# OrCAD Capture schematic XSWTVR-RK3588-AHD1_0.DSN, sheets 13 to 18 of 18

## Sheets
13 13 Audio Codec: size Custom; note: 13 Audio Codec
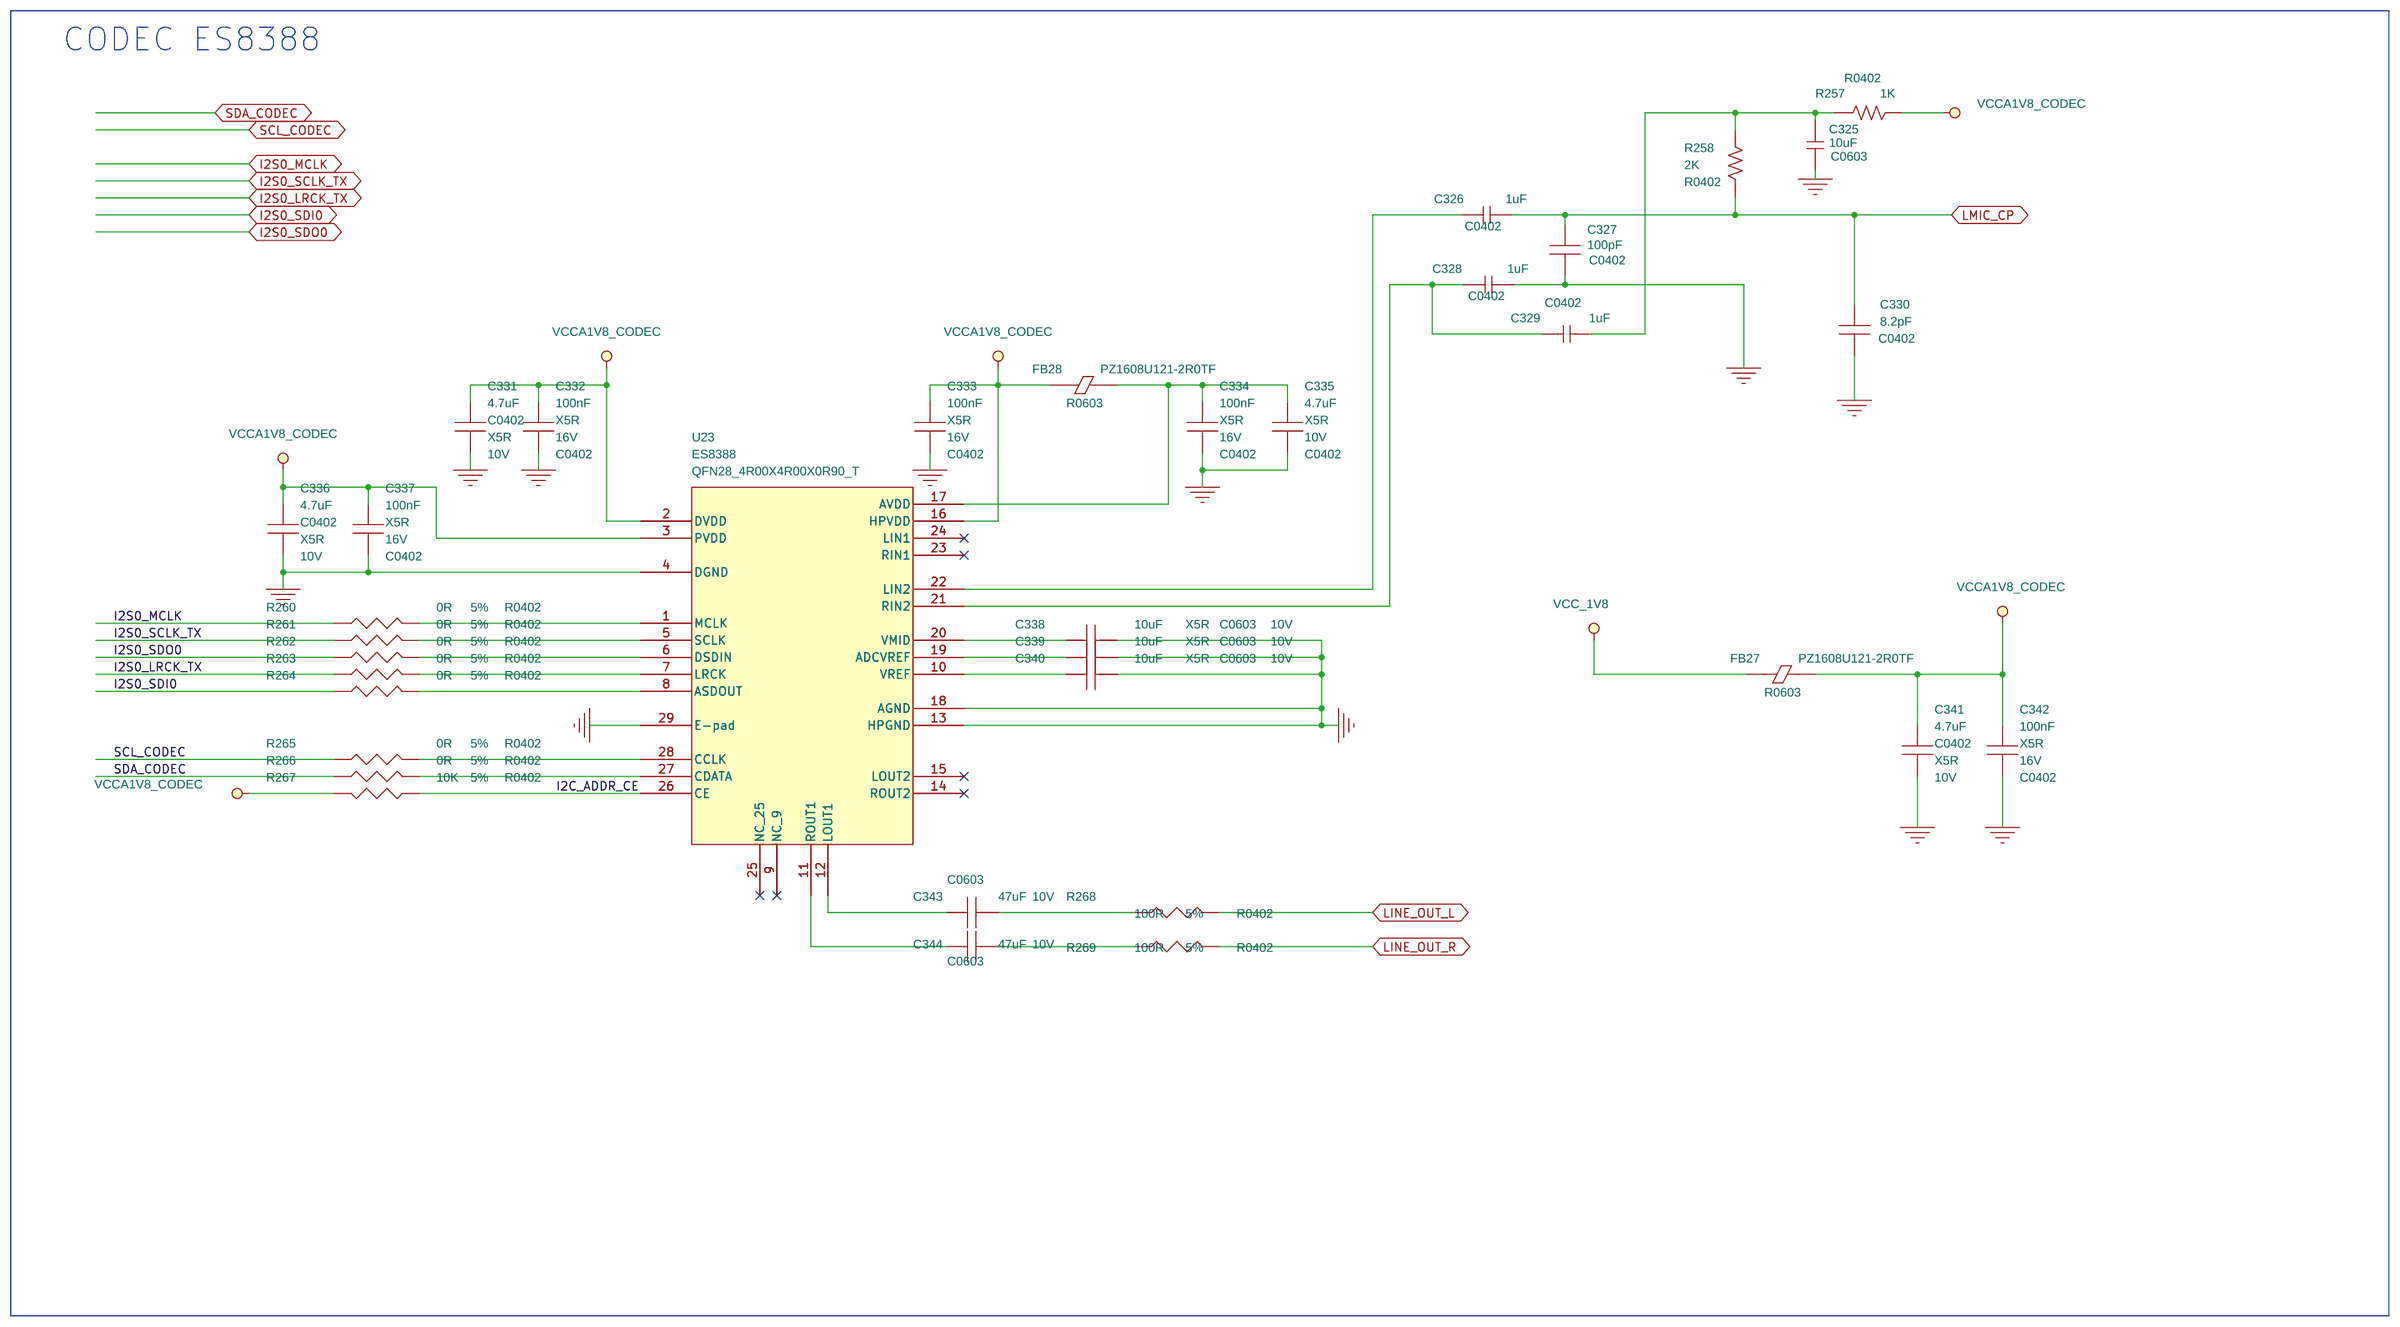
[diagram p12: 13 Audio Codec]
14 14 IO_INPUT_OUTPUT: size Custom; note: 14 IO_INPUT_OUTPUT
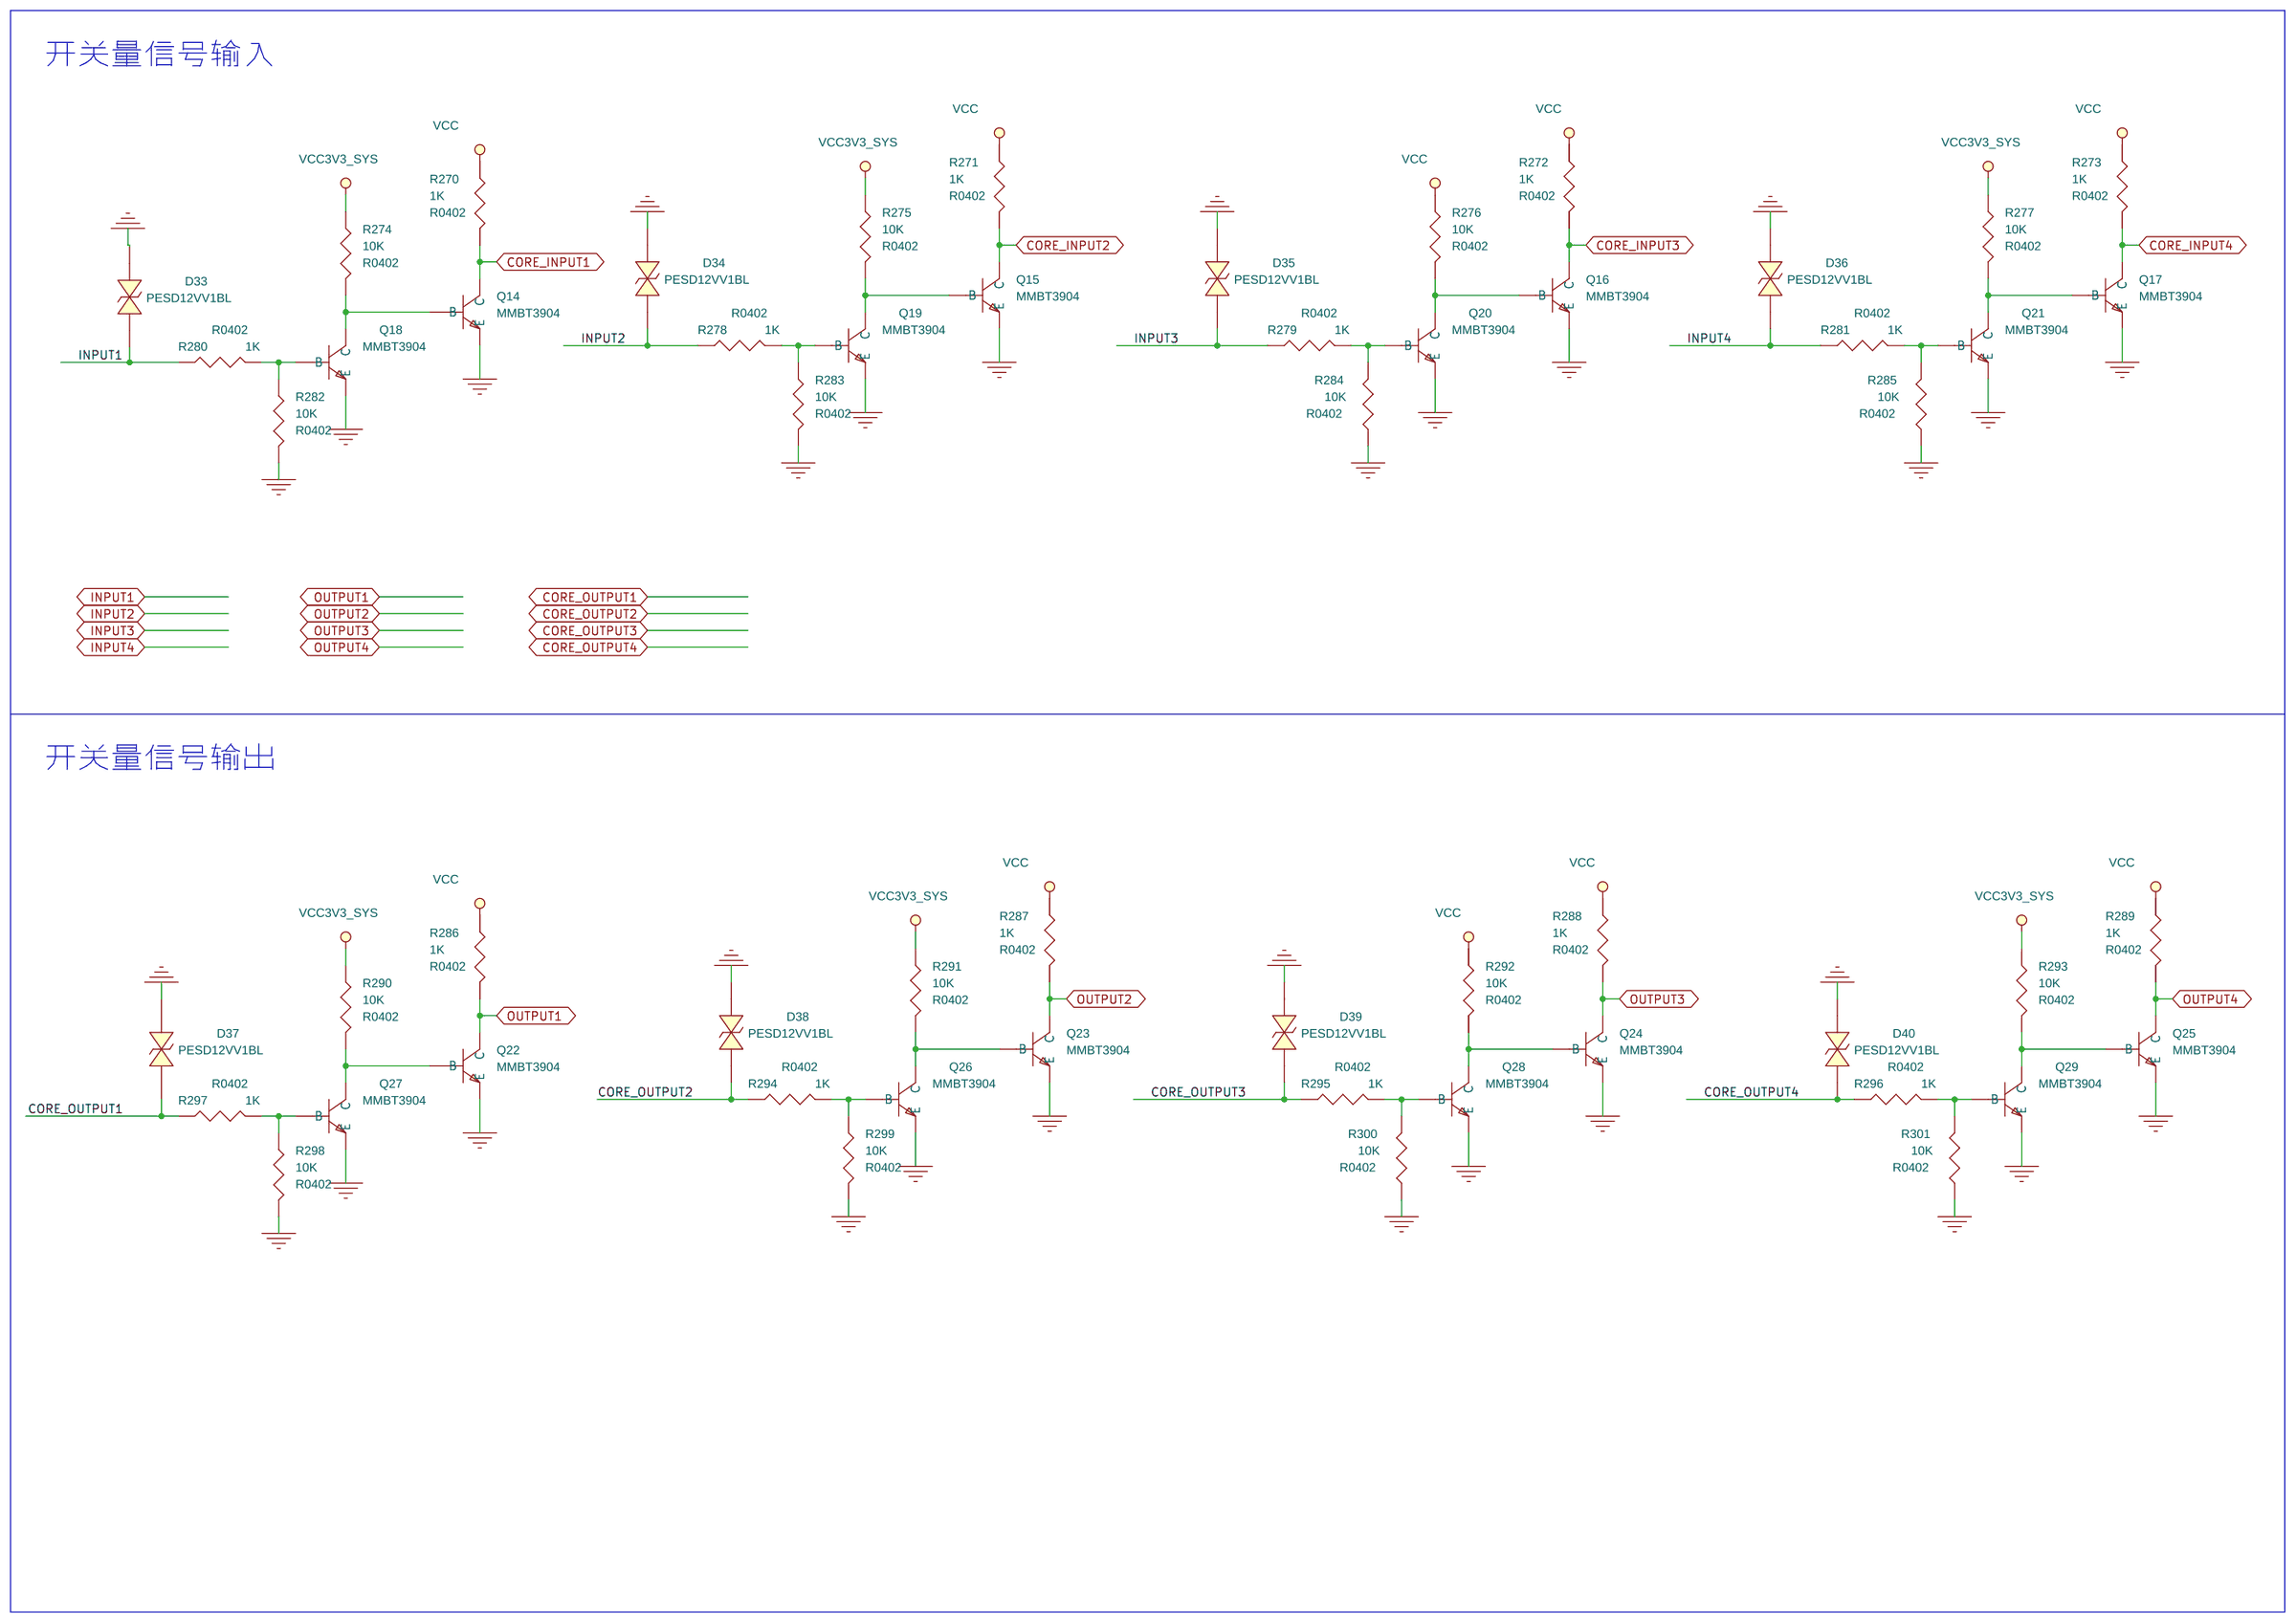
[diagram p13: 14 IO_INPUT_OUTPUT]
15 15 INTERFACE: size Custom; note: 15 INTERFACE
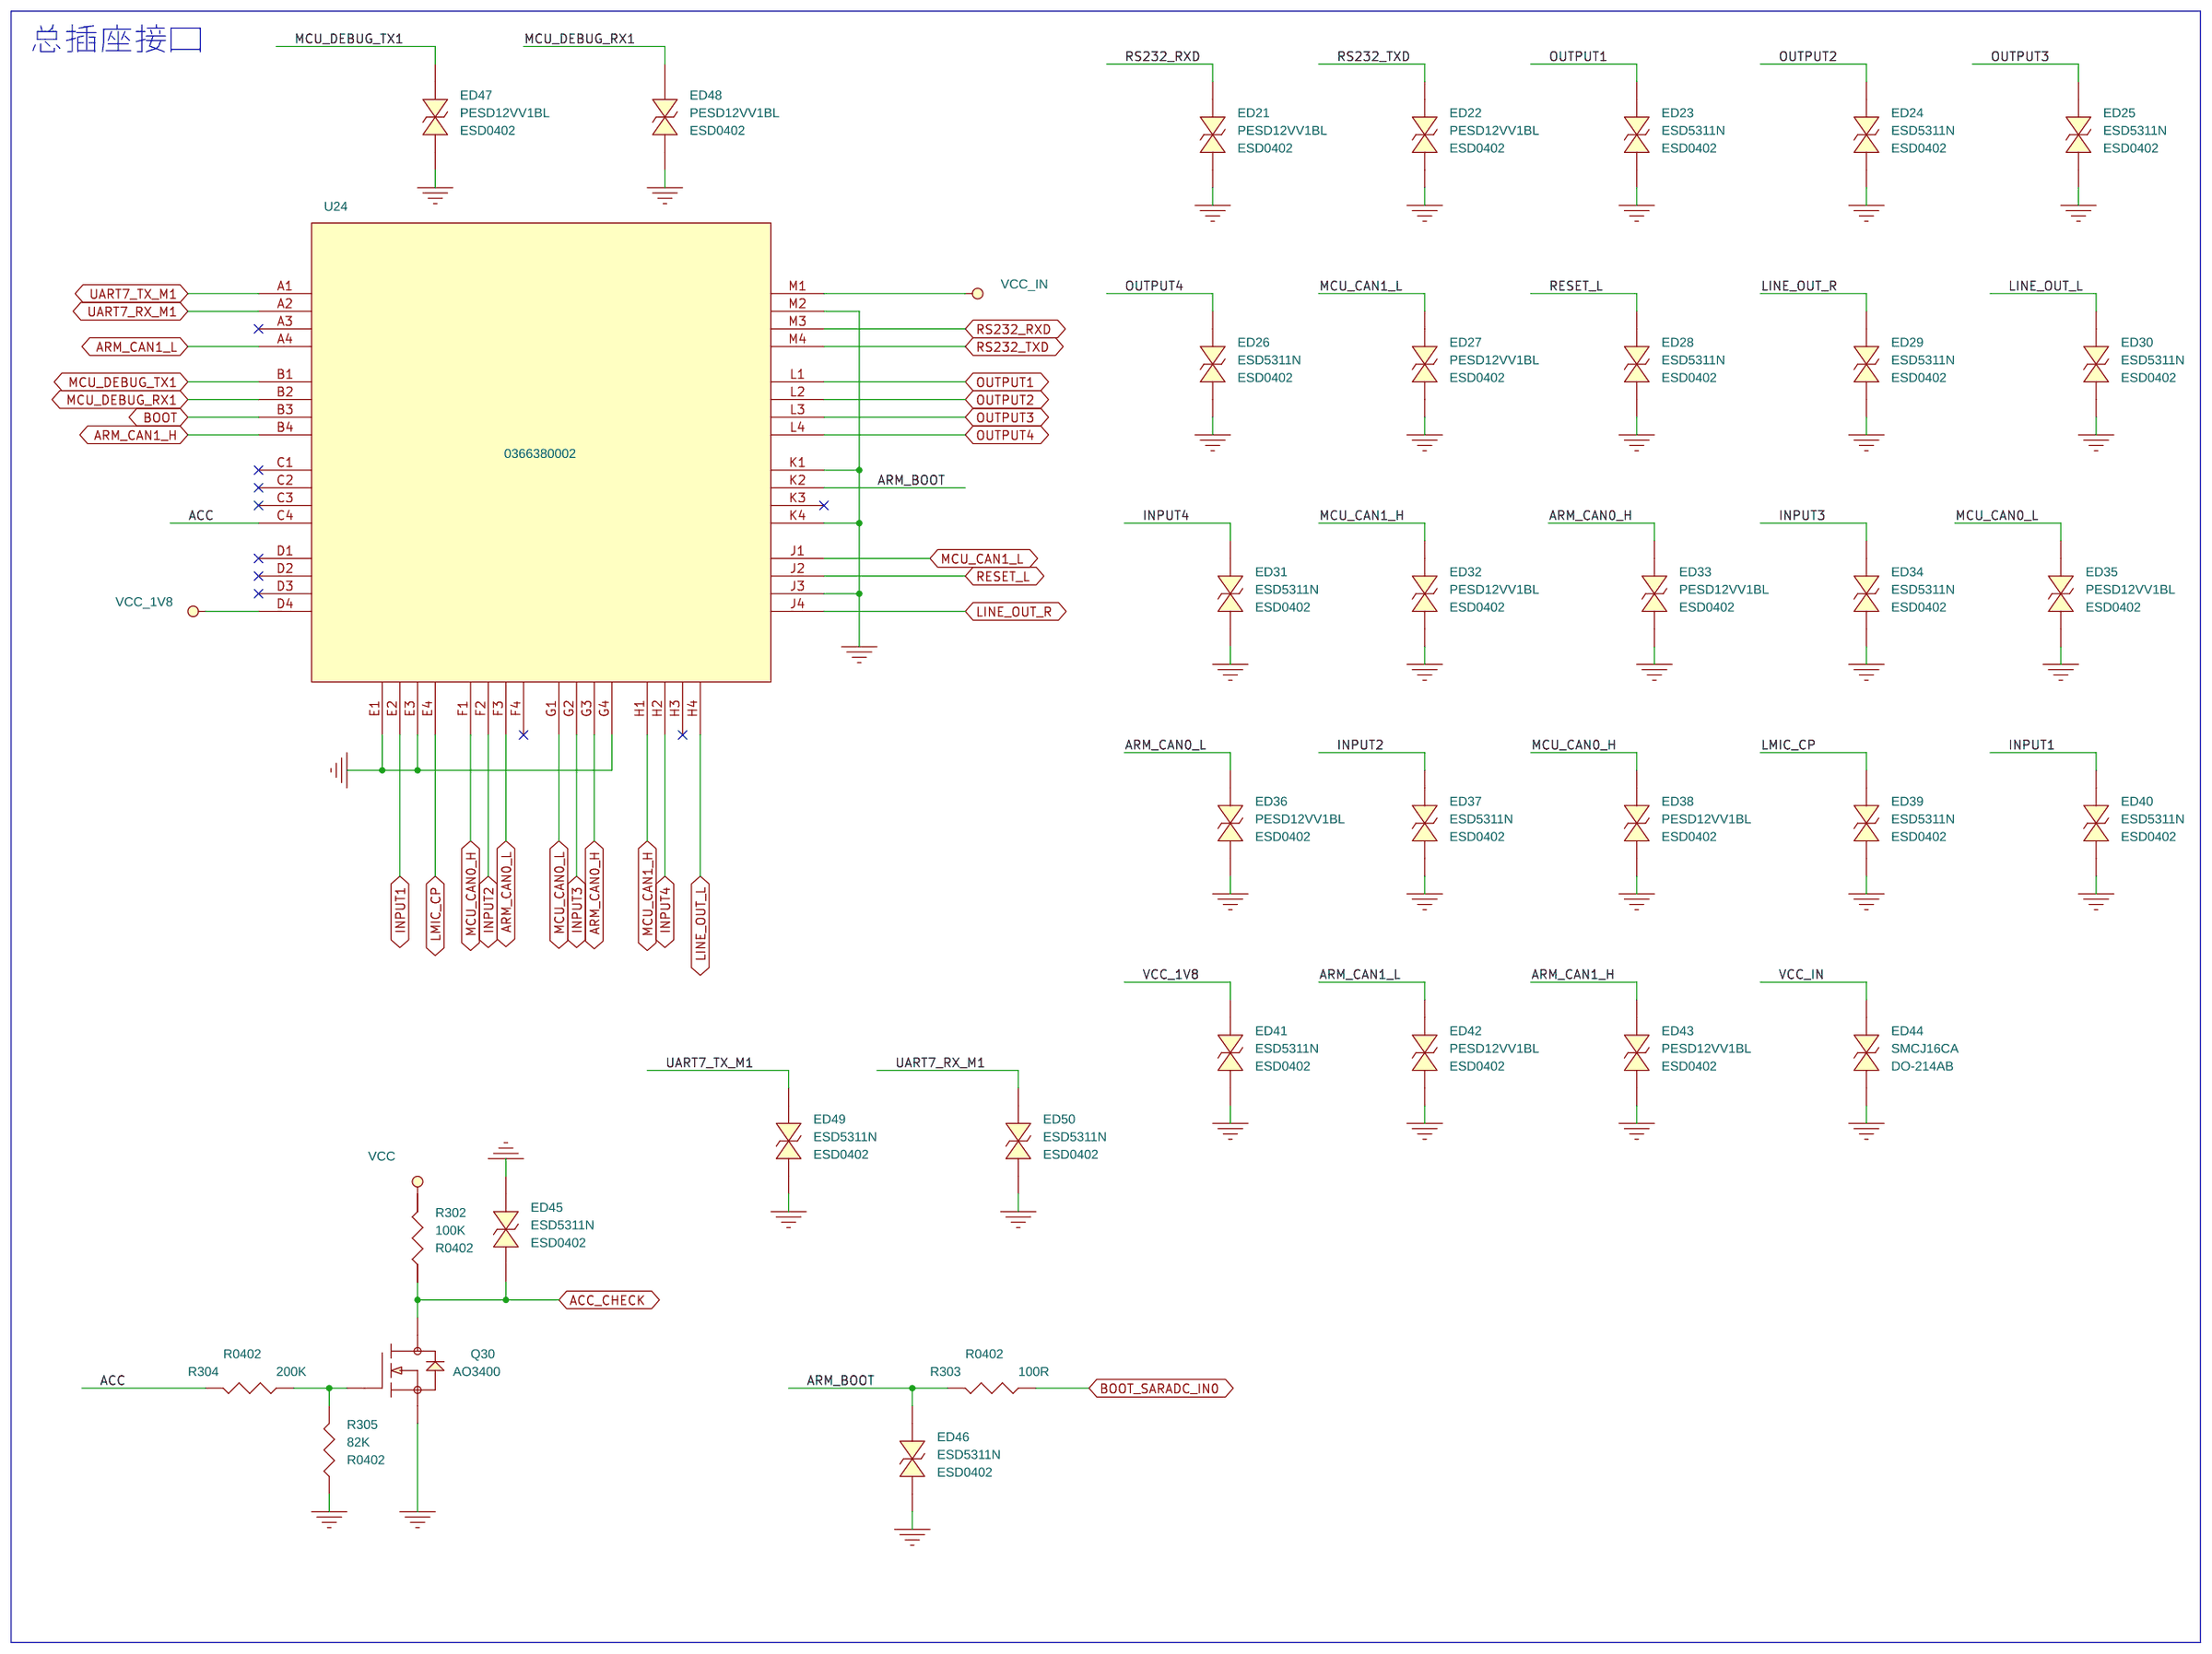
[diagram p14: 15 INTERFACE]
16 16 DEBUG&CAN: size Custom; note: 16 DEBUG&CAN
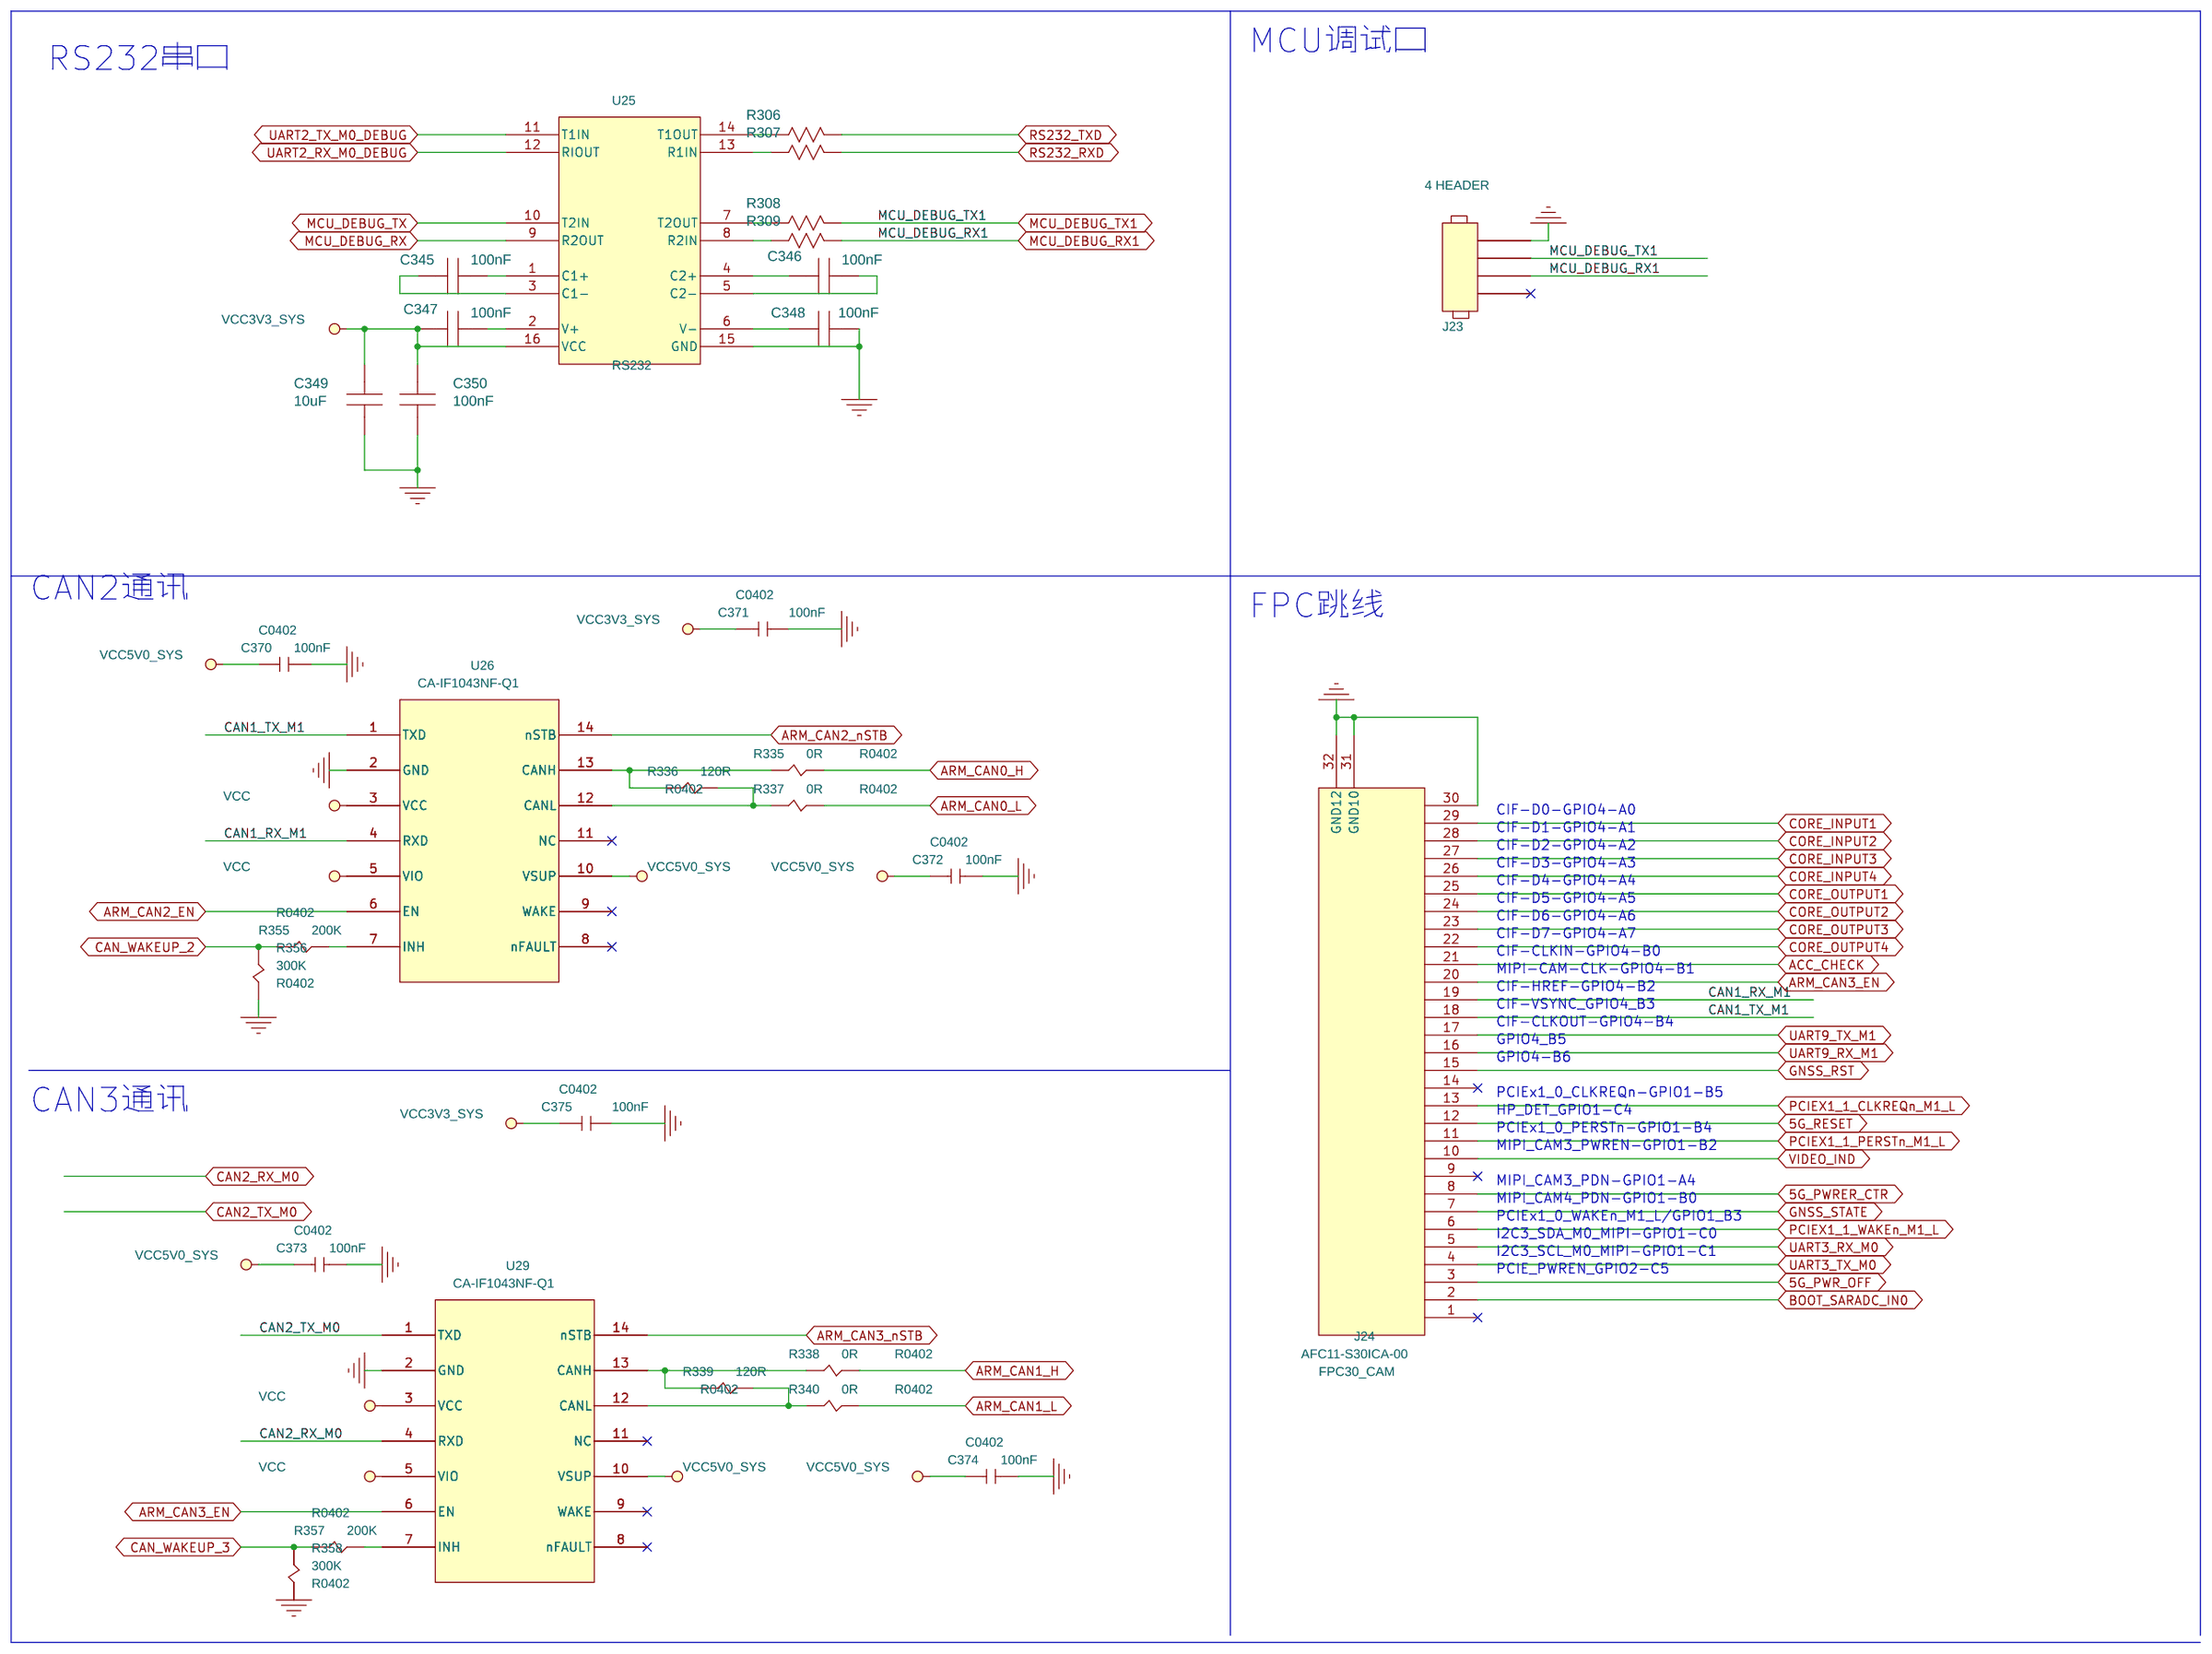
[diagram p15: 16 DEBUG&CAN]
17 17 SATA 3.0*1: size A4; rev: V1.0; note: 12.SATA *2
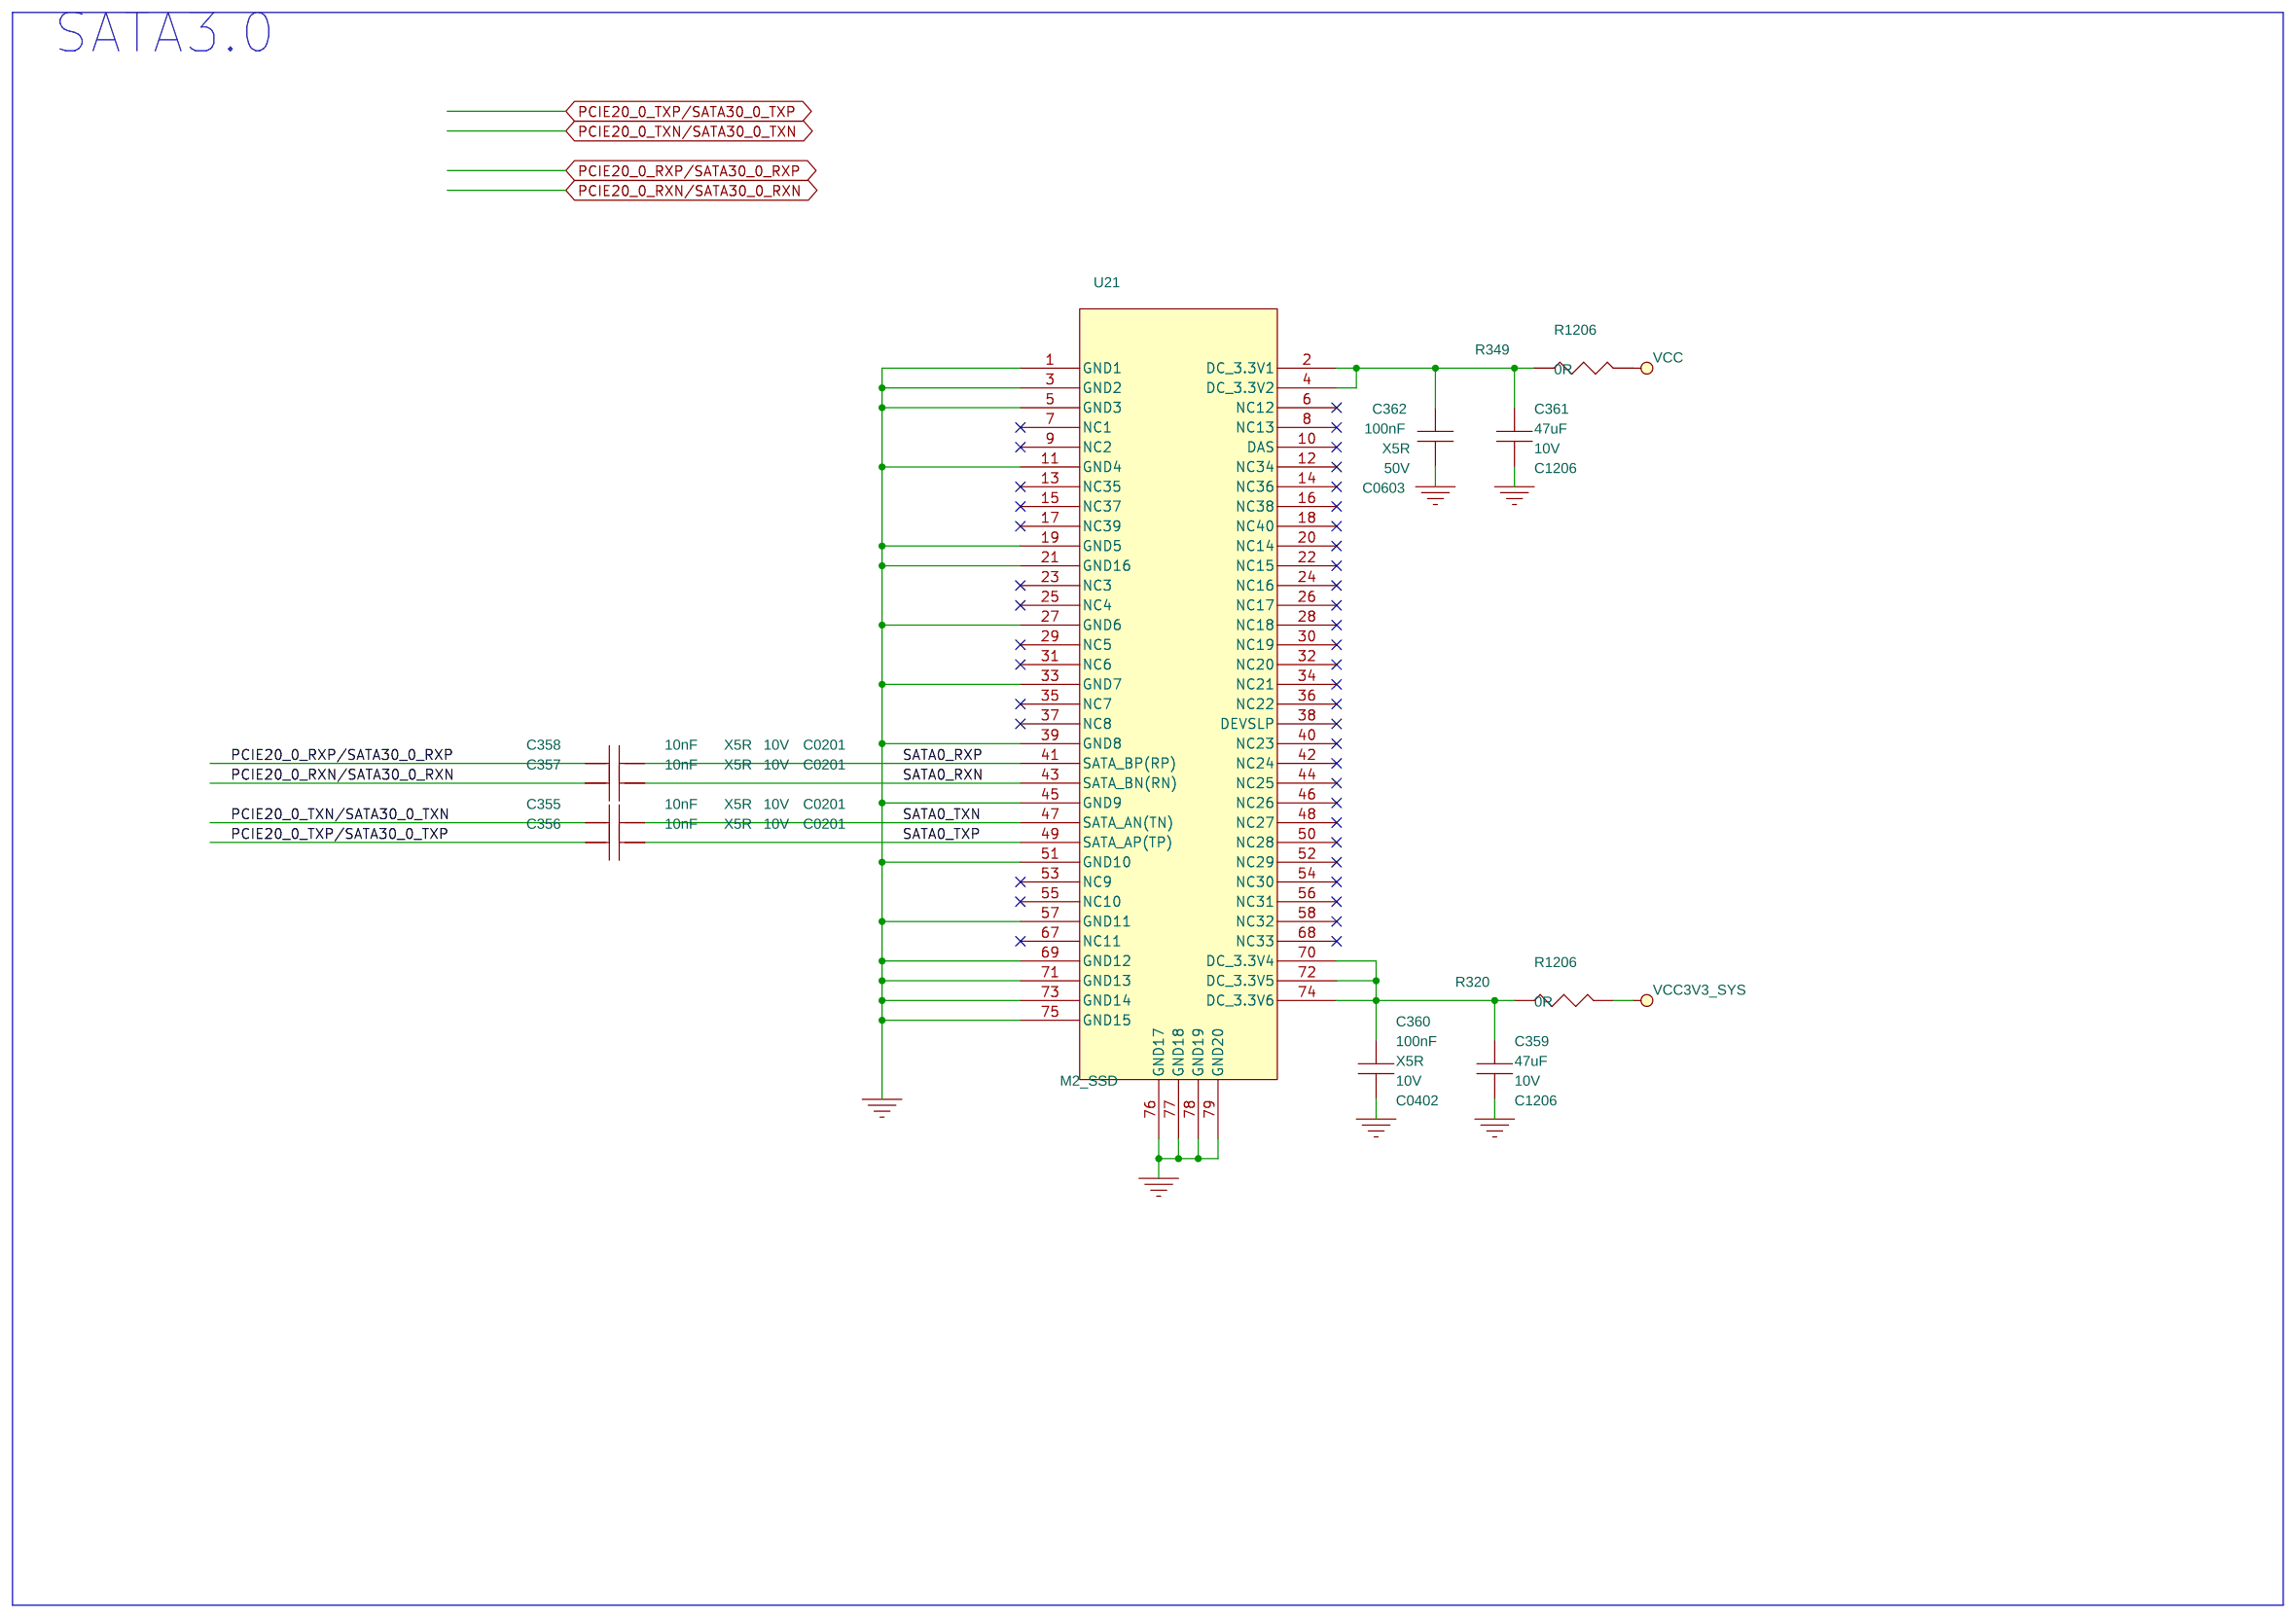
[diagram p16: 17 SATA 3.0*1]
18 18 Mark/Hole: size A4; note: 17 Mark/Hole
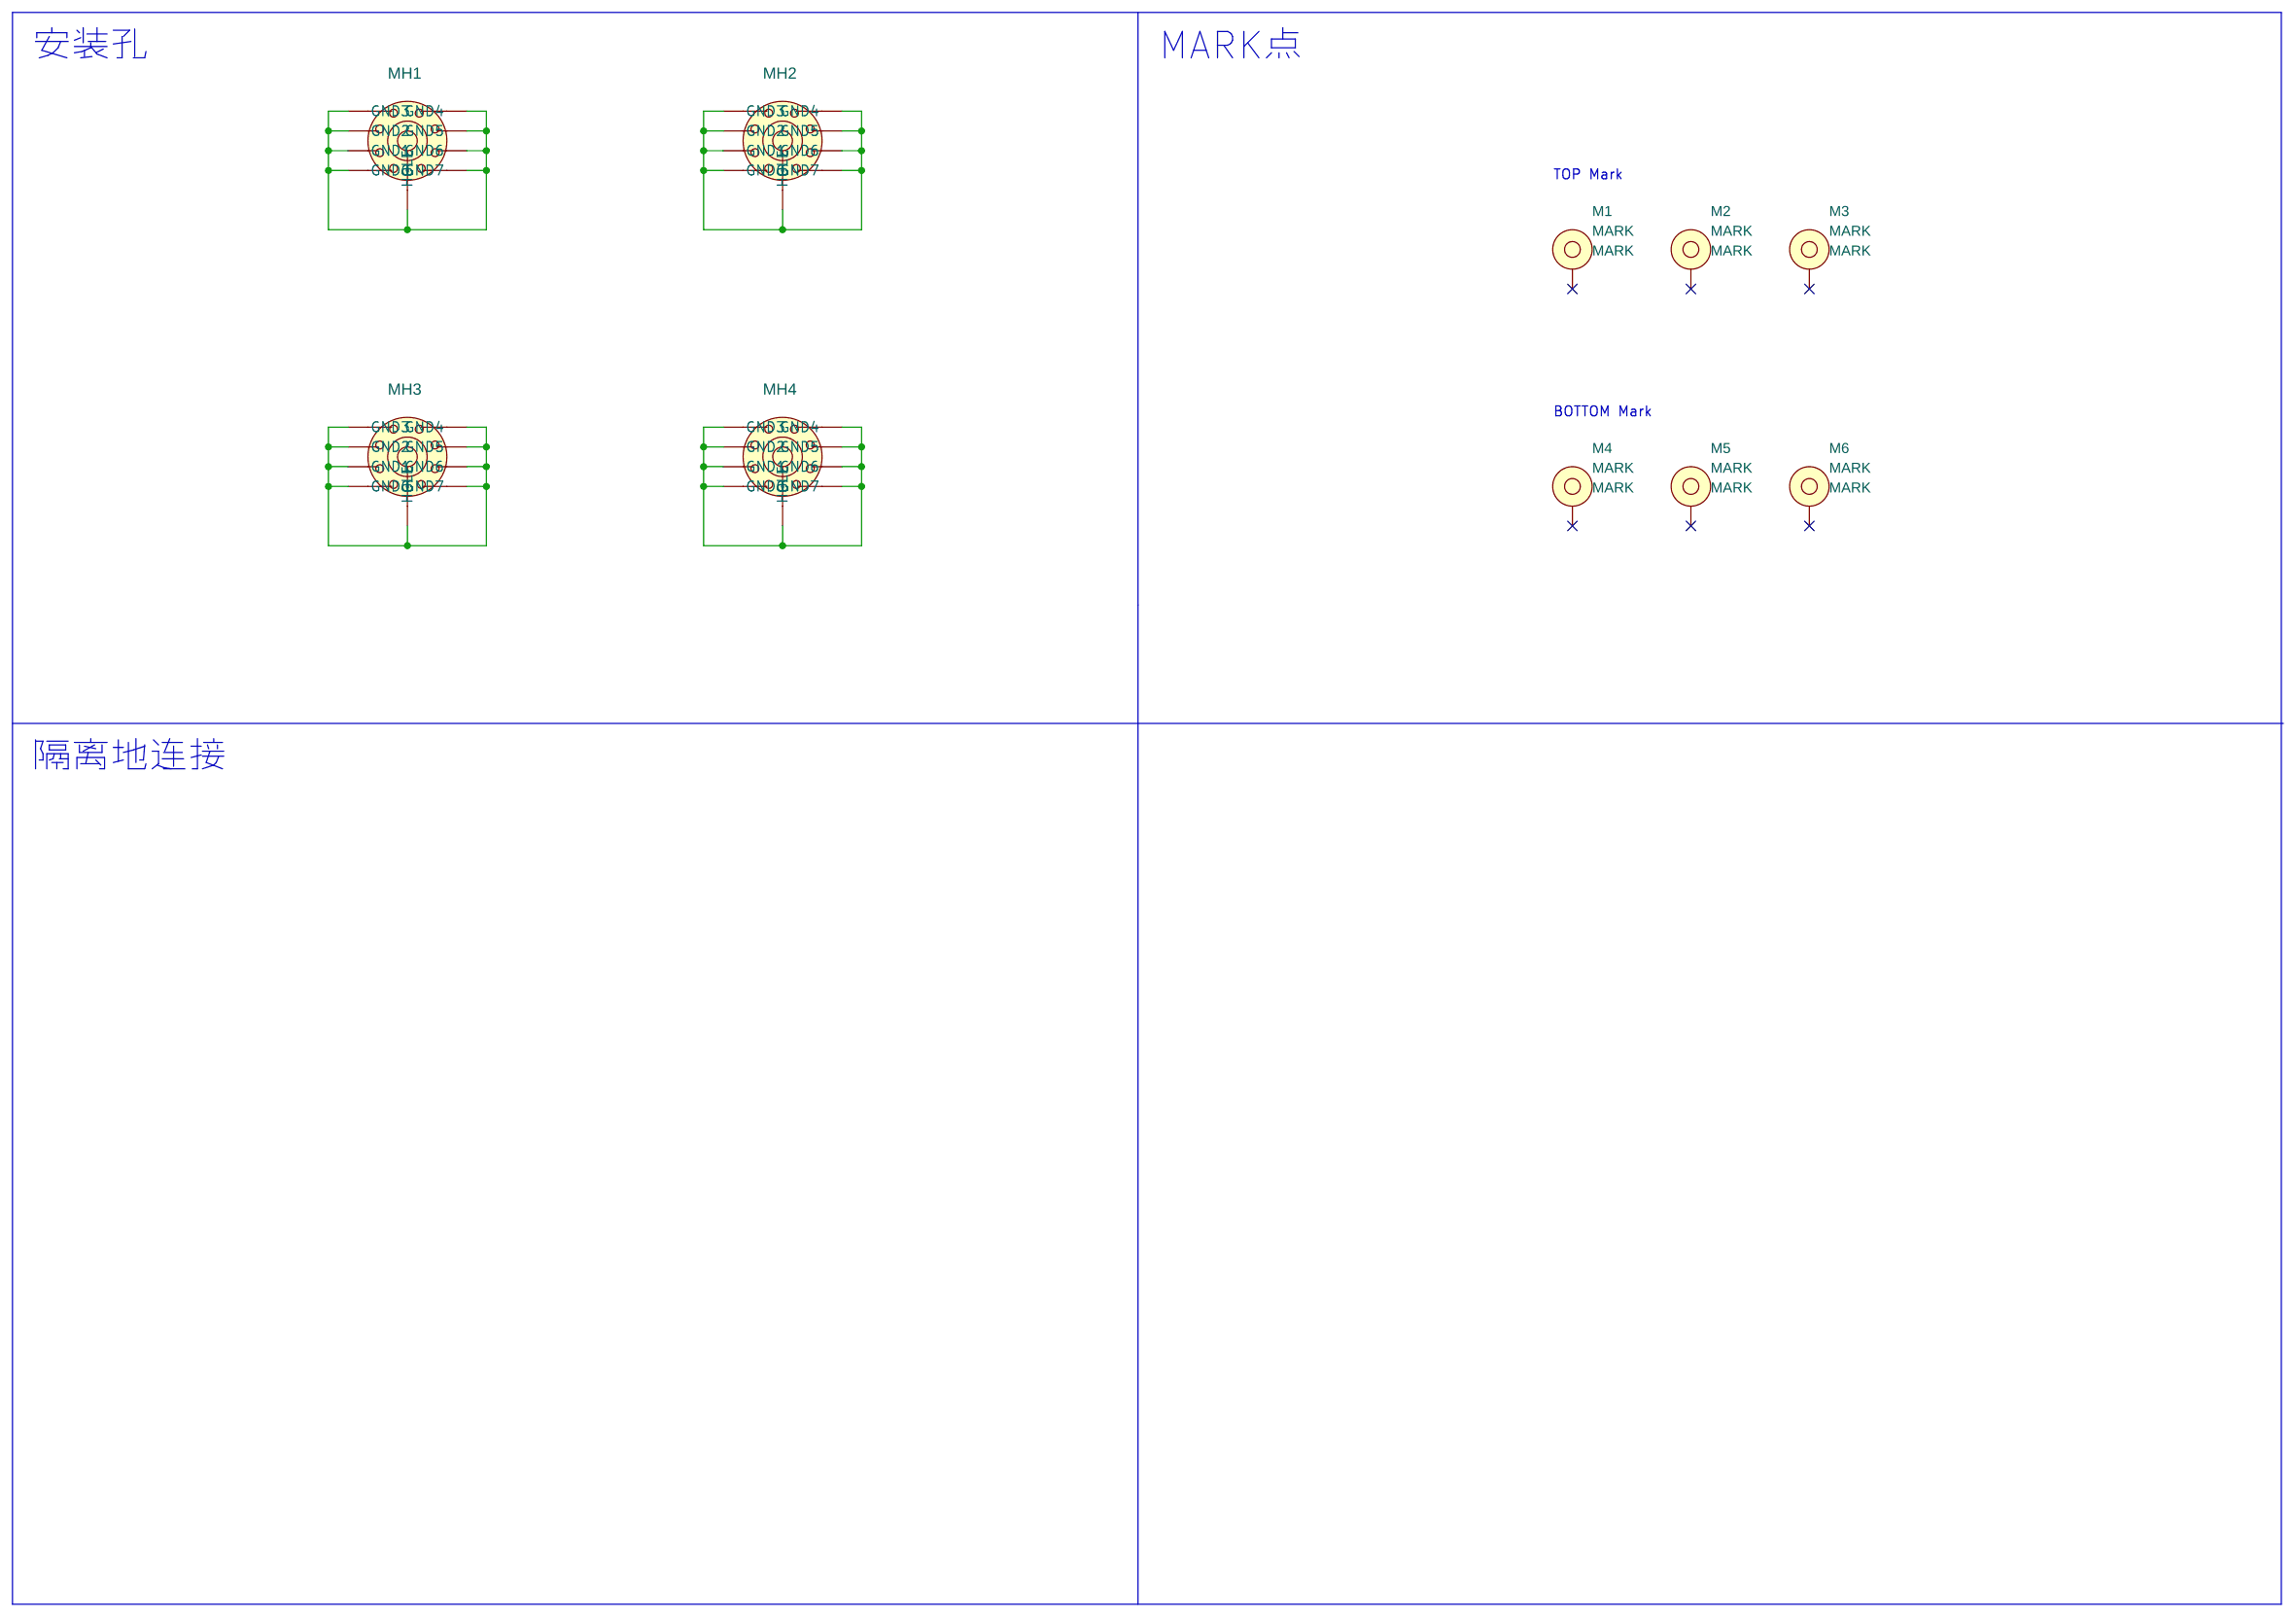
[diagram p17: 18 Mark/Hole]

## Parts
sheet 13 Audio Codec
C325  10uF  [C0603]
C326  1uF  [C0402]
C327  100pF  [C0402]
C328  1uF  [C0402]
C329  1uF  [C0402]
C330  8.2pF  [C0402]
C331  4.7uF  [C0402]
C332  100nF  [C0402]
C333  100nF  [C0402]
C334  100nF  [C0402]
C335  4.7uF  [C0402]
C336  4.7uF  [C0402]
C337  100nF  [C0402]
C338  10uF  [C0603]
C339  10uF  [C0603]
C340  10uF  [C0603]
C341  4.7uF  [C0402]
C342  100nF  [C0402]
C343  47uF  [C0603]
C344  47uF  [C0603]
FB27  PZ1608U121-2R0TF  [R0603]
FB28  PZ1608U121-2R0TF  [R0603]
R257  1K  [R0402]
R258  2K  [R0402]
R260  0R  [R0402]
R261  0R  [R0402]
R262  0R  [R0402]
R263  0R  [R0402]
R264  0R  [R0402]
R265  0R  [R0402]
R266  0R  [R0402]
R267  10K  [R0402]
R268  100R  [R0402]
R269  100R  [R0402]
U23  ES8388  [QFN28_4R00X4R00X0R90_T]
sheet 14 IO_INPUT_OUTPUT
D33  PESD12VV1BL  [esd0402]
D34  PESD12VV1BL  [esd0402]
D35  PESD12VV1BL  [esd0402]
D36  PESD12VV1BL  [esd0402]
D37  PESD12VV1BL  [esd0402]
D38  PESD12VV1BL  [esd0402]
D39  PESD12VV1BL  [esd0402]
D40  PESD12VV1BL  [esd0402]
Q14  MMBT3904  [SOT_23]
Q15  MMBT3904  [SOT_23]
Q16  MMBT3904  [SOT_23]
Q17  MMBT3904  [SOT_23]
Q18  MMBT3904  [SOT_23]
Q19  MMBT3904  [SOT_23]
Q20  MMBT3904  [SOT_23]
Q21  MMBT3904  [SOT_23]
Q22  MMBT3904  [SOT_23]
Q23  MMBT3904  [SOT_23]
Q24  MMBT3904  [SOT_23]
Q25  MMBT3904  [SOT_23]
Q26  MMBT3904  [SOT_23]
Q27  MMBT3904  [SOT_23]
Q28  MMBT3904  [SOT_23]
Q29  MMBT3904  [SOT_23]
R270  1K  [R0402]
R271  1K  [R0402]
R272  1K  [R0402]
R273  1K  [R0402]
R274  10K  [R0402]
R275  10K  [R0402]
R276  10K  [R0402]
R277  10K  [R0402]
R278  1K  [R0402]
R279  1K  [R0402]
R280  1K  [R0402]
R281  1K  [R0402]
R282  10K  [R0402]
R283  10K  [R0402]
R284  10K  [R0402]
R285  10K  [R0402]
R286  1K  [R0402]
R287  1K  [R0402]
R288  1K  [R0402]
R289  1K  [R0402]
R290  10K  [R0402]
R291  10K  [R0402]
R292  10K  [R0402]
R293  10K  [R0402]
R294  1K  [R0402]
R295  1K  [R0402]
R296  1K  [R0402]
R297  1K  [R0402]
R298  10K  [R0402]
R299  10K  [R0402]
R300  10K  [R0402]
R301  10K  [R0402]
sheet 15 INTERFACE
ED21  PESD12VV1BL  [ESD0402]
ED22  PESD12VV1BL  [ESD0402]
ED23  ESD5311N  [ESD0402]
ED24  ESD5311N  [ESD0402]
ED25  ESD5311N  [ESD0402]
ED26  ESD5311N  [ESD0402]
ED27  PESD12VV1BL  [ESD0402]
ED28  ESD5311N  [ESD0402]
ED29  ESD5311N  [ESD0402]
ED30  ESD5311N  [ESD0402]
ED31  ESD5311N  [ESD0402]
ED32  PESD12VV1BL  [ESD0402]
ED33  PESD12VV1BL  [ESD0402]
ED34  ESD5311N  [ESD0402]
ED35  PESD12VV1BL  [ESD0402]
ED36  PESD12VV1BL  [ESD0402]
ED37  ESD5311N  [ESD0402]
ED38  PESD12VV1BL  [ESD0402]
ED39  ESD5311N  [ESD0402]
ED40  ESD5311N  [ESD0402]
ED41  ESD5311N  [ESD0402]
ED42  PESD12VV1BL  [ESD0402]
ED43  PESD12VV1BL  [ESD0402]
ED44  SMCJ16CA  [DO-214AB]
ED45  ESD5311N  [ESD0402]
ED46  ESD5311N  [ESD0402]
ED47  PESD12VV1BL  [ESD0402]
ED48  PESD12VV1BL  [ESD0402]
ED49  ESD5311N  [ESD0402]
ED50  ESD5311N  [ESD0402]
Q30  AO3400  [SOT_23]
R302  100K  [R0402]
R303  100R  [R0402]
R304  200K  [R0402]
R305  82K  [R0402]
U24  0366380002  [SOCKET_PLUG_0366380002]
sheet 16 DEBUG&CAN
C345  100nF  [C0402]
C346  100nF  [C0402]
C347  100nF  [C0402]
C348  100nF  [C0402]
C349  10uF  [C0603]
C350  100nF  [C0402]
C370  100nF  [C0402]
C371  100nF  [C0402]
C372  100nF  [C0402]
C373  100nF  [C0402]
C374  100nF  [C0402]
C375  100nF  [C0402]
J23  4 HEADER  [SOCKET_4P_2P54]
J24  AFC11-S30ICA-00  [FPC30_CAM]
R306  100R  [R0402]
R307  100R  [R0402]
R308  100R  [R0402]
R309  100R  [R0402]
R335  0R  [R0402]
R336  120R  [R0402]
R337  0R  [R0402]
R338  0R  [R0402]
R339  120R  [R0402]
R340  0R  [R0402]
R355  200K  [R0402]
R356  300K  [R0402]
R357  200K  [R0402]
R358  300K  [R0402]
U25  RS232  [IC_SSOP_16]
U26  CA-IF1043NF-Q1  [IC_SOIC_14]
U29  CA-IF1043NF-Q1  [IC_SOIC_14]
sheet 17 SATA 3.0*1
C355  10nF  [C0201]
C356  10nF  [C0201]
C357  10nF  [C0201]
C358  10nF  [C0201]
C359  47uF  [C1206]
C360  100nF  [C0402]
C361  47uF  [C1206]
C362  100nF  [C0603]
R320  0R  [R1206]
R349  0R  [R1206]
U21  M2_SSD  [M2_SSD_2240_2280]
sheet 18 Mark/Hole
M1  MARK  [MARK]
M2  MARK  [MARK]
M3  MARK  [MARK]
M4  MARK  [MARK]
M5  MARK  [MARK]
M6  MARK  [MARK]
MH1  HOLE-8STARS  [hole_3_5mm]
MH2  HOLE-8STARS  [hole_3_5mm]
MH3  HOLE-8STARS  [hole_3_5mm]
MH4  HOLE-8STARS  [hole_3_5mm]

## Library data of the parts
C325 C326 C328 C329 = C_0: REUSE_ANNOTATE: TRUE
C327 C330 = CAP_v2: Capacitor-100nF,+/-10%,X5R,25V-0402; Part Number: 02.0038.00; Part Type: 0402表贴普通电容; REUSE_ANNOTATE: TRUE; 供应商: 国巨 / Murata; 规格型号1: CC0402KRX5R8BB104 / GRM155R71E104KE14D; 联系人: 谢苏云; 手机: 15900554174; 邮箱: susan.xie@murata.com
C331 C335 C336 C341 = CAP_NP: cap,4.70uF,+/-10%,10V,X5R,C0402; Created by: JJJ; Dielectric: X5R; Manufacturer: TDK; Manufacturer PN: C1005X5R1A475K050BC; Priority: A; RK PN: C1005X5R1A475K050BC; Tolerance: 10%; Voltage: 10V
C332-C334 C337 C342 = CAP_NP: cap,100.00nF,+/-10%,16V,X5R,C0402; Created by: JJJ; Dielectric: X5R; Manufacturer: TDK; Manufacturer PN: C1005X5R1C104K050BA; Priority: A; RK PN: C1005X5R1C104K050BA; Tolerance: 10%; Voltage: 16V
C338-C340 = CAP_NP: cap,10.00uF,+/-10%,10V,X5R,C0603; Created by: JJJ; Dielectric: X5R; Manufacturer: TDK; Manufacturer PN: C1608X5R1A106K080AC; Priority: A; RK PN: C1608X5R1A106K080AC; Tolerance: 10%; Voltage: 10V
C343 C344 C359 C361 = CAP_NP_0: cap,10.00uF,+/-10%,25V,X5R,C1206; C_Voltage: 6.3V; Created by: JJJ; Dielectric: X5R; Manufacturer: TDK; Manufacturer PN: C3216X5R1E106K085AC; Priority: A; RK PN: C3216X5R1E106K085AC; Tolerance: 10%; Voltage: 10V
FB27 FB28 = FB: Part Type: R0402
R257 R258 = R: REUSE_ANNOTATE: TRUE
R260-R266 = RESISTOR: 通用厚膜电阻,0R,+/-5%,R0402,1/16W.; Created by: YTL; Manufacturer: YAGEO; Manufacturer PN: RC0402JR-070RL; Part Type: 通用厚膜电阻; Priority: A; RK PN: RC0402JR-070RL; Tolerance: 5%; Wattage: 1/16W
R267 = RESISTOR: 通用厚膜电阻,10K,+/-5%,R0402,1/16W.; Created by: YTL; Manufacturer: YAGEO; Manufacturer PN: RC0402JR-0710KL; Part Type: 通用厚膜电阻; Priority: A; RK PN: RC0402JR-0710KL; Tolerance: 5%; Wattage: 1/16W
R268 R269 = RESISTOR: 通用厚膜电阻,1K1,+/-5%,R0402,1/16W.; Created by: YTL; Manufacturer: YAGEO; Manufacturer PN: RC0402JR-071K1L; Part Type: 通用厚膜电阻; Priority: A; RK PN: RC0402JR-071K1L; Tolerance: 5%; Wattage: 1/16W
U23 = Amplifier_ES8388: ES8388 is a high performance, low power and low cost audio CODEC. It consists of 2-ch ADC, 2-ch DAC, microphone amplifier, headphone amplifier, digital sound effects, and analog mixing and gain functions.; Created by: JJJ; Manufacturer: Everest（顺芯）; Part Type: Amplifier; Priority: A
D33-D40 = DIODE_DIAC
Q14-Q29 = NPN_3
R270-R273 R278-R281 R286-R289 R294-R297 R302-R305 = R_0
R274-R277 R282-R285 R290-R293 R298-R301 = RESISTOR_0: 通用厚膜电阻,232K,+/-1%,R0402,1/16W.; Created by: YTL; Manufacturer: YAGEO; Manufacturer PN: RC0402FR-07232KL; Part Type: 通用厚膜电阻; Priority: A; RK PN: RC0402FR-07232KL; Tolerance: 5%; Wattage: 1/16W
ED21 ED22 ED27 ED32 ED33 ED35 ED36 ED38 ED42-ED44 ED47 ED48 = DIODE_BI_DIR_TRIG: 1-Line, Bi-directional, Transient Voltage Suppressors.0.25pF.; Created by: JJJ; Manufacturer: WillSemi(韦尔半导体); Manufacturer PN: ESD5311N; Part Type: ESD_TVS; Priority: A; RK PN: ESD5311N
ED23-ED26 ED28-ED31 ED34 ED37 ED39-ED41 ED45 ED46 ED49 ED50 = DIODE_BI_DIR_TRIG: 1-Line, Bi-directional, Transient Voltage Suppressors.0.25pF.; Created by: JJJ; Manufacturer: WillSemi(韦尔半导体); Part Type: ESD_TVS; Priority: A
Q30 = 2N6660
U24 = 0366380002
C345-C348 C350 = C_2: %182%%238%%182%%168%%185%%164%%215%%247%%181%%231%%209%%185%(V): 10; %195%%232%%202%%246%: SMD陶瓷电容-10V-1000NF-+/-10%-X5R-0402-BT,TS16949; %208%%161%%192%%224%%195%%251%%179%%198%: SMD陶瓷电容; CODE: 8070612; COMPONENT_HIGH_MAX: 0.55MM; DEVICE: CV05X5R105K10AH; PKG_TYPE: SC0402; SIGNAL_MODEL: DEFAULT_CAPACITOR_1e+06pF_1_2
C349 = C: %182%%238%%182%%168%%185%%164%%215%%247%%181%%231%%209%%185%(V): 25; %195%%232%%202%%246%: SMD陶瓷电容-25V-10000NF-+/-20%-X5R-0805; %208%%161%%192%%224%%195%%251%%179%%198%: SMD陶瓷电容; CODE: 8071629; COMPONENT_HIGH_MAX: 1.45MM; PKG_TYPE: SC0805; SIGNAL_MODEL: DEFAULT_CAPACITOR_1e+07pF_1_2
C370-C375 = CAP_NP_1: price: 0.0125
J23 = 4_HEADER
J24 = LD089WU1_0
R306-R309 = R_v2: %195%%232%%202%%246%: 片式厚膜电阻器-0.0625W-10000ohm-+/-5%-0402-BT; %208%%161%%192%%224%%195%%251%%179%%198%: 片式厚膜电阻器; CODE: 7090815; COMPONENT_HIGH_MAX: 0.4mm; PKG_TYPE: SR0402
R335-R340 R355-R358 = SR_1: price: 0.000688
U25 = RS232_0
U26 U29 = CA-IF1043NF-Q1
C355-C358 = CAP_NP: cap,10.00nF,+/-10%,10V,X5R,C0201; Created by: JJJ; Dielectric: X5R; Manufacturer: TDK; Manufacturer PN: C0603X5R1A103K030BA; Priority: A; RK PN: C0603X5R1A103K030BA; Tolerance: 10%; Voltage: 10V
C360 = CAP_NP: cap,100.00nF,+/-10%,10V,X5R,C0402; C_Voltage: 6.3V; Created by: JJJ; Dielectric: X5R; Manufacturer: TDK; Manufacturer PN: C1005X5R1A104K050BA; Number: 37; Priority: A; RK PN: C1005X5R1A104K050BA; Tolerance: 10%; Voltage: 10V
C362 = CAP_NP: cap,100.00nF,+/-10%,50V,X5R,C0603; Created by: JJJ; Dielectric: X5R; Manufacturer: TDK; Manufacturer PN: C1608X5R1H104K080AA; Priority: A; RK PN: C1608X5R1H104K080AA; Tolerance: 10%; Voltage: 50V
R320 R349 = RESISTOR: 通用厚膜电阻,0R,+/-5%,R1206,1/4W.; Created by: YTL; Manufacturer: YAGEO; Manufacturer PN: RC1206JR-070RL; Part Type: 通用厚膜电阻; Priority: A; RK PN: RC1206JR-070RL; Tolerance: 5%; Wattage: 1/4W
U21 = M2-SSD_1
M1-M6 = MARK: MARK Symble; Created by: JJJ; Priority: A; RK PN: MARK01
MH1-MH4 = HOLE-8STARS_1: %195%%232%%202%%246%: M3螺钉(推荐使用)，对应138MIL星月孔，适用于过波峰焊设计。; PKG_TYPE: HOLE160-8STAR

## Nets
DGND: C325.2 C327.2 C328.1 C330.2 C331.2 C332.2 C333.2 C334.2 C335.2 C336.2 C337.2 C338.2 C339.2 C340.2 C341.2 C342.2 C348.2(B) C349.2(B) C350.1(A) C359.2 C360.2 C361.2 C362.2 C370.2 C371.1 C372.2 C373.2 C374.2 C375.1 D33.2 D34.2 D35.2 D36.2 D37.2 D38.2 D39.2 D40.2 ED21.2 ED22.2 ED23.2 ED24.2 ED25.2 ED26.2 ED27.2 ED28.2 ED29.2 ED30.2 ED31.2 ED32.2 ED33.2 ED34.2 ED35.2 ED36.2 ED37.2 ED38.2 ED39.2 ED40.2 ED41.2 ED42.2 ED43.2 ED44.2 ED45.1 ED46.2 ED47.2 ED48.2 ED49.2 ED50.2 J23.4 J24.30 J24.31(GND10) J24.32(GND12) Q14.2(E) Q15.2(E) Q16.2(E) Q17.2(E) Q18.2(E) Q19.2(E) Q20.2(E) Q21.2(E) Q22.2(E) Q23.2(E) Q24.2(E) Q25.2(E) Q26.2(E) Q27.2(E) Q28.2(E) Q29.2(E) Q30.2(S) R282.2 R283.2 R284.2 R285.2 R298.2 R299.2 R300.2 R301.2 R305.1 R356.1 R358.1 U21.1(GND1) U21.3(GND2) U21.5(GND3) U21.11(GND4) U21.19(GND5) U21.21(GND16) U21.27(GND6) U21.33(GND7) U21.39(GND8) U21.45(GND9) U21.51(GND10) U21.57(GND11) U21.69(GND12) U21.71(GND13) U21.73(GND14) U21.75(GND15) U21.76(GND17) U21.77(GND18) U21.78(GND19) U21.79(GND20) U23.4(DGND) U23.13(HPGND) U23.18(AGND) U23.29(E-pad) U24.E1 U24.E3 U24.G4 U24.J3 U24.K1 U24.K4 U24.M2 U25.15(GND) U26.2(GND) U29.2(GND) ; also on sheet 1 2 3 4 5 6 7 8 9 10 11 12
VCC3V3_SYS: C347.1(A) C349.1(A) C350.2(B) C371.2 C375.2 R270.2 R271.2 R272.2 R273.2 R274.1 R275.1 R276.1 R277.1 R286.2 R287.2 R288.2 R289.2 R290.1 R291.1 R292.1 R293.1 R302.2 R320.2 R349.2 U25.16(VCC) U26.5(VIO) U29.5(VIO) ; also on sheet 1 3 4 5 6 7 8 9 10 11 12
VCC5V0_SYS: C370.1 C372.1 C373.1 C374.1 U26.3(VCC) U26.10(VSUP) U29.3(VCC) U29.10(VSUP) ; also on sheet 1 3 4 8
VCC_1V8: ED41.1 FB27.1 U24.D4 ; also on sheet 3 4 8 9 10
VCC_IN: ED44.1 U24.M1 ; also on sheet 3
VCCA1V8_CODEC: C331.1 C332.1 C333.1 C336.1 C337.1 C341.1 C342.1 FB27.2 FB28.1 R257.2 R267.2 U23.2(DVDD) U23.3(PVDD) U23.16(HPVDD)
5G_PWR_OFF: J24.3 ; also on sheet 5
5G_PWRER_CTR: J24.8 ; also on sheet 5
5G_RESET: J24.12 ; also on sheet 5
ACC: R304.2 U24.C4
ACC_CHECK: ED45.2 J24.21 Q30.3(D) R302.1 ; also on sheet 4
ARM_BOOT: ED46.1 R303.2 U24.K2
ARM_CAN0_H: ED33.1 R335.1 U24.G3
ARM_CAN0_L: ED36.1 R337.1 U24.F3
ARM_CAN1_H: ED43.1 R338.1 U24.B4
ARM_CAN1_L: ED42.1 R340.1 U24.A4
ARM_CAN2_EN: U26.6(EN) ; also on sheet 2
ARM_CAN2_nSTB: U26.14(nSTB) ; also on sheet 2
ARM_CAN3_EN: J24.20 U29.6(EN)
ARM_CAN3_nSTB: U29.14(nSTB) ; also on sheet 2
BOOT: U24.B3 ; also on sheet 4
BOOT_SARADC_IN0: J24.2 R303.1
CAN1_RX_M1: J24.19 U26.4(RXD)
CAN1_TX_M1: J24.18 U26.1(TXD)
CAN2_RX_M0: U29.4(RXD) ; also on sheet 2
CAN2_TX_M0: U29.1(TXD) ; also on sheet 2
CAN_WAKEUP_2: R355.1 R356.2 ; also on sheet 4
CAN_WAKEUP_3: R357.1 R358.2 ; also on sheet 4
CORE_INPUT1: J24.29 Q14.3(C) R270.1
CORE_INPUT2: J24.28 Q15.3(C) R271.1
CORE_INPUT3: J24.27 Q16.3(C) R272.1
CORE_INPUT4: J24.26 Q17.3(C) R273.1
CORE_OUTPUT1: D37.1 J24.25 R297.1
CORE_OUTPUT2: D38.1 J24.24 R294.1
CORE_OUTPUT3: D39.1 J24.23 R295.1
CORE_OUTPUT4: D40.1 J24.22 R296.1
GNSS_RST: J24.15 ; also on sheet 9
GNSS_STATE: J24.7 ; also on sheet 9
I2C_ADDR_CE: R267.1 U23.26(CE)
I2S0_LRCK_TX: R263.1 ; also on sheet 2
I2S0_MCLK: R260.1 ; also on sheet 2
I2S0_SCLK_TX: R261.1 ; also on sheet 2
I2S0_SDI0: R264.1 ; also on sheet 2
I2S0_SDO0: R262.1 ; also on sheet 2
INPUT1: D33.1 ED40.1 R280.1 U24.E2
INPUT2: D34.1 ED37.1 R278.1 U24.F2
INPUT3: D35.1 ED34.1 R279.1 U24.G2
INPUT4: D36.1 ED31.1 R281.1 U24.H2
LINE_OUT_L: ED30.1 R268.2 U24.H4
LINE_OUT_R: ED29.1 R269.2 U24.J4
LMIC_CP: C326.1 C327.1 C330.1 ED39.1 R258.1 U24.E4
MCU_CAN0_H: ED38.1 U24.F1 ; also on sheet 4
MCU_CAN0_L: ED35.1 U24.G1 ; also on sheet 4
MCU_CAN1_H: ED32.1 U24.H1 ; also on sheet 4
MCU_CAN1_L: ED27.1 U24.J1 ; also on sheet 4
MCU_DEBUG_RX: U25.9(R2OUT) ; also on sheet 4
MCU_DEBUG_RX1: ED48.1 J23.2 R309.2(B) U24.B2
MCU_DEBUG_TX: U25.10(T2IN) ; also on sheet 4
MCU_DEBUG_TX1: ED47.1 J23.3 R308.2(B) U24.B1
OUTPUT1: ED23.1 Q22.3(C) R286.1 U24.L1
OUTPUT2: ED24.1 Q23.3(C) R287.1 U24.L2
OUTPUT3: ED25.1 Q24.3(C) R288.1 U24.L3
OUTPUT4: ED26.1 Q25.3(C) R289.1 U24.L4
PCIE20_0_RXN/SATA30_0_RXN: C357.1 ; also on sheet 2
PCIE20_0_RXP/SATA30_0_RXP: C358.1 ; also on sheet 2
PCIE20_0_TXN/SATA30_0_TXN: C355.1 ; also on sheet 2
PCIE20_0_TXP/SATA30_0_TXP: C356.1 ; also on sheet 2
PCIEX1_1_CLKREQn_M1_L: J24.13 ; also on sheet 5
PCIEX1_1_PERSTn_M1_L: J24.11 ; also on sheet 5
PCIEX1_1_WAKEn_M1_L: J24.6 ; also on sheet 5
RESET_L: ED28.1 U24.J2 ; also on sheet 2
RS232_RXD: ED21.1 R307.2(B) U24.M3
RS232_TXD: ED22.1 R306.2(B) U24.M4
SATA0_RXN: C357.2 U21.43(SATA_BN(RN))
SATA0_RXP: C358.2 U21.41(SATA_BP(RP))
SATA0_TXN: C355.2 U21.47(SATA_AN(TN))
SATA0_TXP: C356.2 U21.49(SATA_AP(TP))
SCL_CODEC: R265.1 ; also on sheet 2
SDA_CODEC: R266.1 ; also on sheet 2
UART2_RX_M0_DEBUG: U25.12(RIOUT) ; also on sheet 2
UART2_TX_M0_DEBUG: U25.11(T1IN) ; also on sheet 2
UART3_RX_M0: J24.5 ; also on sheet 9
UART3_TX_M0: J24.4 ; also on sheet 9
UART7_RX_M1: ED50.1 U24.A2 ; also on sheet 2
UART7_TX_M1: ED49.1 U24.A1 ; also on sheet 2
UART9_RX_M1: J24.16 ; also on sheet 4
UART9_TX_M1: J24.17 ; also on sheet 4
VIDEO_IND: J24.10 ; also on sheet 7
N16931377: Q14.1(B) Q18.3(C) R274.2
N16931417: Q18.1(B) R280.2 R282.1
N16931861: Q15.1(B) Q19.3(C) R275.2
N16931902: Q19.1(B) R278.2 R283.1
N16985810: Q16.1(B) Q20.3(C) R276.2
N16985852: Q20.1(B) R279.2 R284.1
N17583651: C343.2 R268.1
N17583654: C344.2 R269.1
N17587612: Q17.1(B) Q21.3(C) R277.2
N17587654: Q21.1(B) R281.2 R285.1
N17590009: Q23.1(B) Q26.3(C) R291.2
N17590020: Q24.1(B) Q28.3(C) R292.2
N17590031: Q25.1(B) Q29.3(C) R293.2
N17590042: Q22.1(B) Q27.3(C) R290.2
N17590162: Q26.1(B) R294.2 R299.1
N17590173: Q28.1(B) R295.2 R300.1
N17590184: Q29.1(B) R296.2 R301.1
N17590195: Q27.1(B) R297.2 R298.1
N17604176: R306.1(A) U25.14(T1OUT)
N17604199: R307.1(A) U25.13(R1IN)
N17604219: C345.1(A) U25.3(C1-)
N17604223: C345.2(B) U25.1(C1+)
N17604225: C346.1(A) U25.4(C2+)
N17604227: C346.2(B) U25.5(C2-)
N17604259: C347.2(B) U25.2(V+)
N17604261: C348.1(A) U25.6(V-)
N17613828: R308.1(A) U25.7(T2OUT)
N17613831: R309.1(A) U25.8(R2IN)
N17720923: Q30.1(G) R304.1 R305.2
N17726410: C325.1 C329.1 R257.1 R258.2
N17726460: C326.2 U23.22(LIN2)
N17726498: C328.2 C329.2 U23.21(RIN2)
N17791454: C334.1 C335.1 FB28.2 U23.17(AVDD)
N17906339: R335.2 R336.2 U26.13(CANH)
N17906381: R336.1 R337.2 U26.12(CANL)
N17907326: R338.2 R339.2 U29.13(CANH)
N17907351: R339.1 R340.2 U29.12(CANL)
N18080998: MH1.1(GND0) MH1.2(GND1) MH1.3(GND2) MH1.4(GND3) MH1.5(GND4) MH1.6(GND5) MH1.7(GND6) MH1.8(GND7) MH1.9(HOLE)
N18081006: MH2.1(GND0) MH2.2(GND1) MH2.3(GND2) MH2.4(GND3) MH2.5(GND4) MH2.6(GND5) MH2.7(GND6) MH2.8(GND7) MH2.9(HOLE)
N18081112: MH3.1(GND0) MH3.2(GND1) MH3.3(GND2) MH3.4(GND3) MH3.5(GND4) MH3.6(GND5) MH3.7(GND6) MH3.8(GND7) MH3.9(HOLE)
N18081120: MH4.1(GND0) MH4.2(GND1) MH4.3(GND2) MH4.4(GND3) MH4.5(GND4) MH4.6(GND5) MH4.7(GND6) MH4.8(GND7) MH4.9(HOLE)
N18115892: C361.1 C362.1 R349.1 U21.2(DC_3.3V1) U21.4(DC_3.3V2)
N18121133: C359.1 C360.1 R320.1 U21.70(DC_3.3V4) U21.72(DC_3.3V5) U21.74(DC_3.3V6)
N18177766: R355.2 U26.7(INH)
N18177976: R357.2 U29.7(INH)
N25391738: C343.1 U23.12(LOUT1)
N25392270: C339.1 U23.19(ADCVREF)
N25392272: C340.1 U23.10(VREF)
N25392276: C338.1 U23.20(VMID)
N25392525: C344.1 U23.11(ROUT1)
N25392529: R260.2 U23.1(MCLK)
N25392543: R261.2 U23.5(SCLK)
N25392545: R262.2 U23.6(DSDIN)
N25392559: R263.2 U23.7(LRCK)
N25392573: R264.2 U23.8(ASDOUT)
N25392575: R265.2 U23.28(CCLK)
N25392589: R266.2 U23.27(CDATA)

Not connected (* = marked no-connect by the designer): J23 1*; J24 1* 9* 14*; M1 1*; M2 1*; M3 1*; M4 1*; M5 1*; M6 1*; U21 6(NC12)* 7(NC1)* 8(NC13)* 9(NC2)* 10(DAS)* 12(NC34)* 13(NC35)* 14(NC36)* 15(NC37)* 16(NC38)* 17(NC39)* 18(NC40)* 20(NC14)* 22(NC15)* 23(NC3)* 24(NC16)* 25(NC4)* 26(NC17)* 28(NC18)* 29(NC5)* 30(NC19)* 31(NC6)* 32(NC20)* 34(NC21)* 35(NC7)* 36(NC22)* 37(NC8)* 38(DEVSLP)* 40(NC23)* 42(NC24)* 44(NC25)* 46(NC26)* 48(NC27)* 50(NC28)* 52(NC29)* 53(NC9)* 54(NC30)* 55(NC10)* 56(NC31)* 58(NC32)* 67(NC11)* 68(NC33)*; U23 9(NC)* 14(ROUT2)* 15(LOUT2)* 23(RIN1)* 24(LIN1)* 25(NC)*; U24 A3* C1* C2* C3* D1* D2* D3* F4* H3* K3*; U26 8(nFAULT)* 9(WAKE)* 11(NC)*; U29 8(nFAULT)* 9(WAKE)* 11(NC)*

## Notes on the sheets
sheet 13
- CODEC ES8388
sheet 14
- 开关量信号输入
- 开关量信号输出
sheet 15
- 总插座接口
sheet 16
- MCU调试口
- RS232串口
- CAN2通讯
- FPC跳线
- CIF-D0-GPIO4-A0
- CIF-D1-GPIO4-A1
- CIF-D2-GPIO4-A2
- CIF-D3-GPIO4-A3
- CIF-D4-GPIO4-A4
- CIF-D5-GPIO4-A5
- CIF-D6-GPIO4-A6
- CIF-D7-GPIO4-A7
- CIF-CLKIN-GPIO4-B0
- MIPI-CAM-CLK-GPIO4-B1
- CIF-HREF-GPIO4-B2
- CIF-VSYNC_GPIO4_B3
- CIF-CLKOUT-GPIO4-B4
- GPIO4_B5
- GPIO4-B6
- CAN3通讯
- PCIEx1_0_CLKREQn-GPIO1-B5
- HP_DET_GPIO1-C4
- PCIEx1_0_PERSTn-GPIO1-B4
- MIPI_CAM3_PWREN-GPIO1-B2
- MIPI_CAM3_PDN-GPIO1-A4
- MIPI_CAM4_PDN-GPIO1-B0
- PCIEx1_0_WAKEn_M1_L/GPIO1_B3
- I2C3_SCL_M0_MIPI-GPIO1-C1
- I2C3_SDA_M0_MIPI-GPIO1-C0
- PCIE_PWREN_GPIO2-C5
sheet 17
- SATA3.0
sheet 18
- 安装孔
- MARK点
- TOP Mark
- BOTTOM Mark
- 隔离地连接
